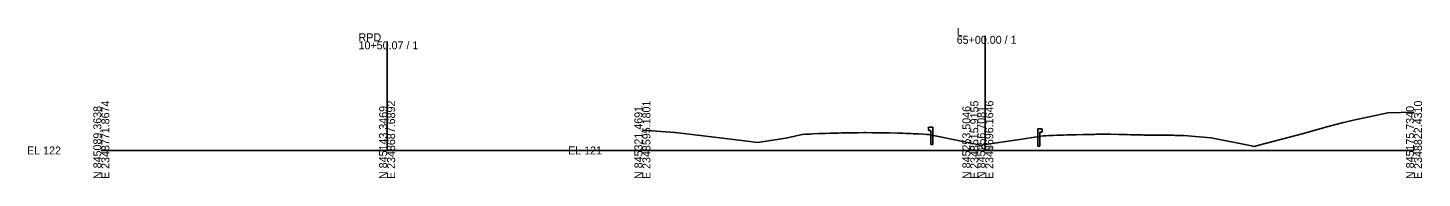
# Model space of a CAD drawing. Extents: x -26 to 2348767, y -10 to 845205.
# Drawn here: x 2004.9 to 2492.8, y 490.3 to 543 of the extents above; entities that cross this region are included whole.
import ezdxf

# ---------------------------------------------------------------- set-up
doc = ezdxf.new("R2010")
doc.units = 0
for name, color, linetype in [('Exist Cross Section Cell', 7, 'Continuous'), ('Exist XS Center Line Elevation Label', 7, 'Continuous'), ('Exist XS Ground Line', 7, 'Continuous'), ('Prop CMT Guardrail Graphics', 7, 'Continuous')]:
    doc.layers.add(name, color=color, linetype=linetype)

msp = doc.modelspace()

# ---------------------------------------------------------------- linework, layer by layer
at = {"layer": 'Exist Cross Section Cell'}
for p, q in [((2130.64, 500), (2130.64, 538.24)), ((2339.93, 500), (2339.93, 540.17)), ((2030.64, 500), (2130.64, 500)), ((2130.64, 500), (2334.7, 500)), ((2219.96, 500), (2339.93, 500)), ((2339.93, 500), (2489.93, 500))]:
    msp.add_line(p, q, dxfattribs=at)
at = {"layer": 'Exist XS Ground Line'}
msp.add_lwpolyline([(2219.96, 507.1), (2231.29, 506.25), (2233.42, 506.09), (2235.44, 505.85), (2247.96, 504.3), (2256.66, 503.21), (2260.2, 502.79), (2270.17, 504.37), (2271.65, 504.61), (2272.84, 504.88), (2275.79, 505.6), (2276.14, 505.57), (2277.06, 505.66), (2278.64, 505.77), (2279.62, 505.81), (2281.58, 505.9), (2282.56, 505.94), (2284.02, 506), (2285.56, 506.03), (2286.13, 506.06), (2286.84, 506.07), (2288.51, 506.1), (2289.45, 506.13), (2290.92, 506.15), (2291.47, 506.17), (2292.51, 506.18), (2294.46, 506.22), (2294.86, 506.22), (2295.49, 506.23), (2297.51, 506.26), (2298, 506.26), (2300.42, 506.24), (2300.84, 506.23), (2303.37, 506.2), (2303.91, 506.19), (2304.77, 506.17), (2305.73, 506.14), (2306.34, 506.13), (2309.38, 506.06), (2309.87, 506.05), (2311.06, 506.01), (2312.23, 505.98), (2312.91, 505.96), (2313.98, 505.91), (2314.73, 505.88), (2315.22, 505.86), (2316.58, 505.81), (2318.32, 505.73), (2319.49, 505.65), (2320.11, 505.61), (2324.77, 504.63), (2338.28, 501.85), (2339.93, 502.09), (2351.16, 503.74), (2360.34, 505.12), (2361.07, 505.16), (2362.17, 505.21), (2362.77, 505.23), (2363.64, 505.27), (2364.97, 505.32), (2365.77, 505.35), (2367.24, 505.4), (2368.72, 505.44), (2369.36, 505.46), (2369.98, 505.48), (2370.69, 505.51), (2371.68, 505.53), (2374.17, 505.58), (2374.65, 505.59), (2376.3, 505.63), (2377.62, 505.65), (2378.1, 505.65), (2378.88, 505.66), (2379.92, 505.67), (2380.55, 505.68), (2382.01, 505.68), (2382.31, 505.68), (2383.79, 505.67), (2386.49, 505.63), (2387.08, 505.62), (2388.08, 505.59), (2388.98, 505.58), (2389.53, 505.56), (2390.77, 505.53), (2392.8, 505.47), (2394.1, 505.43), (2394.79, 505.43), (2395.42, 505.42), (2397.39, 505.41), (2398.42, 505.4), (2400.3, 505.39), (2401.38, 505.38), (2402, 505.37), (2403.41, 505.35), (2404.32, 505.34), (2405.43, 505.32), (2405.8, 505.31), (2406.31, 505.3), (2407.31, 505.29), (2408.77, 505.21), (2409.52, 505.25), (2413.37, 504.93), (2418.98, 504.38), (2432.44, 501.75), (2434.1, 501.41), (2435.6, 501.81), (2450.81, 505.88), (2459.93, 508.35), (2465.24, 509.79), (2468.75, 510.62), (2480.78, 513.21), (2489.93, 513.39)], dxfattribs=at)
at = {"layer": 'Prop CMT Guardrail Graphics'}
for p, q in [((2320.2, 508.12), (2319.93, 507.83)), ((2319.93, 507.83), (2320.2, 507.54)), ((2320.2, 507.54), (2319.93, 507.25)), ((2321.53, 508.12), (2320.2, 508.12)), ((2321.53, 502.12), (2321.53, 508.12)), ((2358.32, 501.56), (2358.32, 507.56)), ((2358.32, 507.56), (2359.66, 507.56)), ((2359.66, 507.56), (2359.93, 507.27)), ((2319.93, 507.25), (2320.2, 506.96)), ((2320.2, 506.96), (2320.86, 506.96)), ((2320.86, 506.96), (2320.86, 502.12)), ((2359.66, 506.39), (2358.99, 506.39)), ((2358.99, 506.39), (2358.99, 501.56)), ((2359.93, 507.27), (2359.66, 506.98)), ((2359.66, 506.98), (2359.93, 506.69)), ((2359.93, 506.69), (2359.66, 506.39)), ((2320.86, 502.12), (2321.53, 502.12)), ((2358.99, 501.56), (2358.32, 501.56))]:
    msp.add_line(p, q, dxfattribs=at)

# ---------------------------------------------------------------- texts
at = {"layer": 'Exist Cross Section Cell'}
for s, p in [('L', (2329.93, 540.17)), ('10+50.07 / 1', (2120.64, 535.44)), ('RPD', (2120.64, 538.24)), ('65+00.00 / 1', (2329.93, 537.37)), ('EL 122', (2004.64, 498.6)), ('EL 121', (2193.96, 498.6))]:
    msp.add_text(s, height=2.8, dxfattribs=at).set_placement(p)
for s, p in [('E 2348771.8674', (2033.44, 490)), ('E 2348687.6892', (2133.44, 490)), ('E 2348595.1801', (2222.76, 490)), ('E 2348515.9155', (2337.5, 490)), ('E 2348696.1646', (2342.73, 490)), ('E 2348822.4310', (2492.73, 490)), ('N 845089.3638', (2030.64, 490)), ('N 845143.3469', (2130.64, 490)), ('N 845321.4691', (2219.96, 490)), ('N 845253.5046', (2334.7, 490)), ('N 845256.7081', (2339.93, 490)), ('N 845175.7340', (2489.93, 490))]:
    msp.add_text(s, height=2.8, rotation=90, dxfattribs=at).set_placement(p)
at = {"layer": 'Exist XS Center Line Elevation Label'}
msp.add_text('123.09', height=1.2, dxfattribs=at).set_placement((2337.43, 500.49))

doc.saveas('drawing.dxf')
